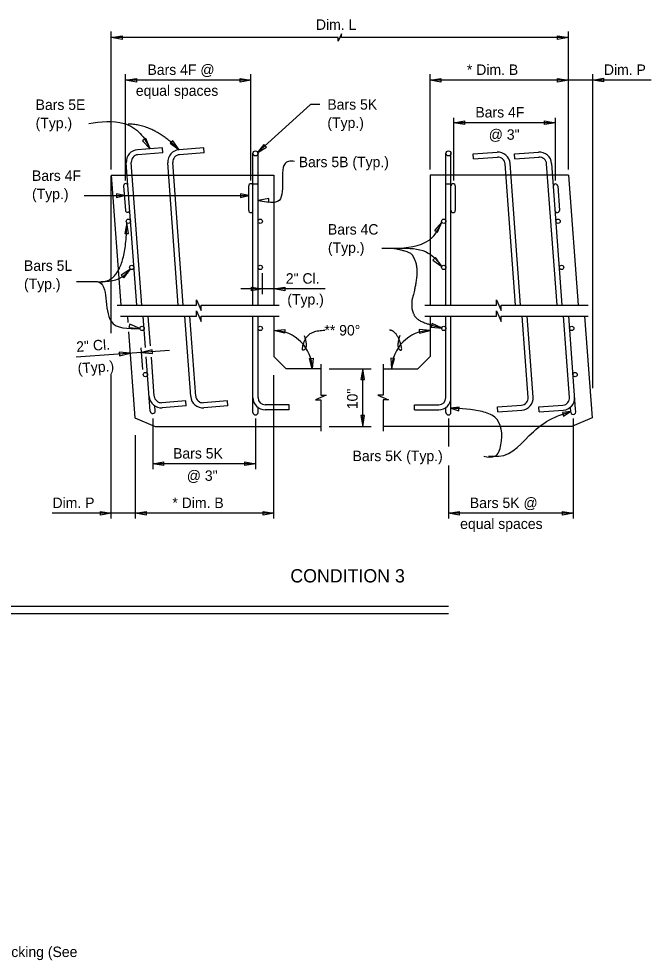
# Model space of a CAD drawing. Extents: x 0.5 to 29.5, y 0.9 to 17.7.
# Drawn here: x 20.37 to 29.51, y 4.1 to 17.7 of the extents above; entities that cross this region are included whole.
import ezdxf

# ---------------------------------------------------------------- set-up
doc = ezdxf.new("R2010")
doc.units = 0
for name, color, linetype in [('BeamConc', 7, 'Continuous'), ('Dimension', 7, 'Continuous'), ('Rebar', 7, 'Continuous'), ('TextStructures', 7, 'Continuous')]:
    doc.layers.add(name, color=color, linetype=linetype)

# ---------------------------------------------------------------- blocks, each defined once
blk = doc.blocks.new('Terminator-Arrow')
at = {"layer": 'Dimension'}
blk.add_lwpolyline([(0, 0), (-0.00041, 0.000069), (-0.00041, -0.000069)], close=True, dxfattribs=at)

msp = doc.modelspace()

# ---------------------------------------------------------------- linework, layer by layer
at = {"layer": 'BeamConc'}
for p, q in [((21.701, 15.447), (24.052, 15.447)), ((21.701, 15.447), (21.84, 13.569)), ((24.052, 15.447), (24.052, 13.569)), ((28.309, 15.447), (26.309, 15.447)), ((26.309, 15.447), (26.309, 13.569)), ((28.309, 15.447), (28.448, 13.569)), ((21.935, 13.407), (21.941, 13.316)), ((24.052, 13.407), (24.052, 12.825)), ((26.309, 13.407), (26.309, 12.825)), ((28.542, 13.407), (28.651, 11.94)), ((21.951, 13.183), (22.043, 11.94)), ((24.229, 12.648), (24.052, 12.825)), ((26.132, 12.648), (26.309, 12.825)), ((24.729, 12.648), (24.229, 12.648)), ((25.632, 12.648), (26.132, 12.648)), ((22.043, 11.94), (22.335, 11.815)), ((28.651, 11.94), (28.359, 11.815)), ((22.335, 11.815), (24.729, 11.815)), ((28.359, 11.815), (25.632, 11.815))]:
    msp.add_line(p, q, dxfattribs=at)
at = {"layer": 'Dimension'}
for p, q in [((21.701, 15.529), (21.701, 17.519)), ((21.701, 15.529), (21.701, 17.519)), ((28.309, 15.529), (28.309, 17.519)), ((28.309, 15.529), (28.309, 17.519)), ((21.909, 15.368), (21.909, 16.903)), ((21.909, 15.368), (21.909, 16.903)), ((23.719, 15.368), (23.719, 16.903)), ((23.719, 15.368), (23.719, 16.903)), ((26.309, 15.529), (26.309, 16.903)), ((26.309, 15.529), (26.309, 16.903)), ((28.66, 12.37), (28.66, 16.903)), ((28.66, 12.37), (28.66, 16.903)), ((23.719, 16.819), (21.909, 16.819)), ((23.719, 16.819), (21.909, 16.819)), ((29.505, 16.819), (26.309, 16.819)), ((29.505, 16.819), (26.309, 16.819)), ((26.651, 15.368), (26.651, 16.274)), ((26.651, 15.368), (26.651, 16.274)), ((28.12, 16.204), (26.651, 16.204)), ((28.12, 16.204), (26.651, 16.204)), ((28.12, 15.368), (28.12, 16.274)), ((28.12, 15.368), (28.12, 16.274)), ((21.701, 13.161), (21.701, 15.433)), ((21.701, 13.161), (21.701, 15.433)), ((21.308, 15.151), (23.687, 15.151)), ((21.308, 15.151), (23.687, 15.151)), ((23.885, 13.728), (23.885, 14.029)), ((23.885, 13.728), (23.885, 14.029)), ((24.794, 13.803), (23.575, 13.803)), ((24.794, 13.803), (23.575, 13.803)), ((22.158, 12.639), (22.136, 12.949)), ((22.158, 12.639), (22.136, 12.949)), ((22.541, 12.914), (21.193, 12.814)), ((22.541, 12.914), (21.193, 12.814)), ((21.701, 10.485), (21.701, 12.564)), ((21.701, 10.485), (21.701, 12.564)), ((24.052, 10.485), (24.052, 12.556)), ((24.052, 10.485), (24.052, 12.556)), ((24.851, 12.648), (25.459, 12.648)), ((24.851, 12.648), (25.459, 12.648)), ((25.338, 11.815), (25.338, 12.648)), ((25.338, 11.815), (25.338, 12.648)), ((22.302, 11.932), (22.302, 11.2)), ((22.302, 11.932), (22.302, 11.2)), ((23.786, 11.932), (23.786, 11.2)), ((23.786, 11.932), (23.786, 11.2)), ((26.575, 11.932), (26.575, 11.526)), ((26.575, 11.932), (26.575, 11.526)), ((28.378, 11.932), (28.378, 10.485)), ((28.378, 11.932), (28.378, 10.485)), ((24.851, 11.815), (25.459, 11.815)), ((24.851, 11.815), (25.459, 11.815)), ((22.052, 10.485), (22.052, 11.687)), ((22.052, 10.485), (22.052, 11.687)), ((23.786, 11.276), (22.302, 11.276)), ((23.786, 11.276), (22.302, 11.276)), ((26.575, 11.253), (26.575, 10.485)), ((26.575, 11.253), (26.575, 10.485)), ((24.052, 10.561), (20.846, 10.561)), ((24.052, 10.561), (20.846, 10.561)), ((28.378, 10.561), (26.575, 10.561)), ((28.378, 10.561), (26.575, 10.561)), ((26.575, 9.216), (18.476, 9.216)), ((26.575, 9.216), (18.476, 9.216)), ((26.575, 9.108), (18.476, 9.108)), ((26.575, 9.108), (18.476, 9.108))]:
    msp.add_line(p, q, dxfattribs=at)
for points in [[(28.309, 17.434), (25.028, 17.434), (25.028, 17.486), (25.005, 17.434), (24.983, 17.382), (24.983, 17.434), (21.701, 17.434)], [(28.309, 17.434), (25.028, 17.434), (25.028, 17.486), (25.005, 17.434), (24.983, 17.382), (24.983, 17.434), (21.701, 17.434)], [(24.716, 16.469), (24.583, 16.469), (23.812, 15.766)], [(24.716, 16.469), (24.583, 16.469), (23.812, 15.766)], [(21.787, 13.569), (22.934, 13.569), (22.934, 13.646), (22.968, 13.569), (23.002, 13.491), (23.002, 13.569), (24.128, 13.569)], [(21.787, 13.569), (22.934, 13.569), (22.934, 13.646), (22.968, 13.569), (23.002, 13.491), (23.002, 13.569), (24.128, 13.569)], [(26.234, 13.569), (27.269, 13.569), (27.269, 13.646), (27.303, 13.569), (27.336, 13.491), (27.336, 13.569), (28.594, 13.569)], [(26.234, 13.569), (27.269, 13.569), (27.269, 13.646), (27.303, 13.569), (27.336, 13.491), (27.336, 13.569), (28.594, 13.569)], [(21.835, 13.407), (22.934, 13.407), (22.934, 13.484), (22.968, 13.407), (23.002, 13.329), (23.002, 13.407), (24.128, 13.407)], [(21.835, 13.407), (22.934, 13.407), (22.934, 13.484), (22.968, 13.407), (23.002, 13.329), (23.002, 13.407), (24.128, 13.407)], [(26.234, 13.407), (27.269, 13.407), (27.269, 13.484), (27.303, 13.407), (27.336, 13.329), (27.336, 13.407), (28.594, 13.407)], [(26.234, 13.407), (27.269, 13.407), (27.269, 13.484), (27.303, 13.407), (27.336, 13.329), (27.336, 13.407), (28.594, 13.407)], [(24.729, 12.715), (24.729, 12.265), (24.807, 12.265), (24.652, 12.198), (24.729, 12.198), (24.729, 11.748)], [(24.729, 12.715), (24.729, 12.265), (24.807, 12.265), (24.652, 12.198), (24.729, 12.198), (24.729, 11.748)], [(25.632, 12.715), (25.632, 12.265), (25.554, 12.265), (25.709, 12.198), (25.632, 12.198), (25.632, 11.748)], [(25.632, 12.715), (25.632, 12.265), (25.554, 12.265), (25.709, 12.198), (25.632, 12.198), (25.632, 11.748)]]:
    msp.add_lwpolyline(points, dxfattribs=at)
for points in [[(22.262, 15.827), (22.2, 15.973), (22.155, 15.944)], [(22.262, 15.827), (22.2, 15.973), (22.155, 15.944)], [(22.682, 15.814), (22.591, 15.943), (22.553, 15.906)], [(22.682, 15.814), (22.591, 15.943), (22.553, 15.906)], [(23.812, 15.766), (23.945, 15.852), (23.909, 15.891)], [(23.812, 15.766), (23.945, 15.852), (23.909, 15.891)], [(21.893, 15.151), (21.776, 15.177), (21.776, 15.124)], [(21.893, 15.151), (21.776, 15.177), (21.776, 15.124)], [(23.688, 15.151), (23.57, 15.177), (23.57, 15.124)], [(23.688, 15.151), (23.57, 15.177), (23.57, 15.124)], [(23.823, 15.082), (23.979, 15.056), (23.979, 15.109)], [(23.823, 15.082), (23.979, 15.056), (23.979, 15.109)], [(21.927, 14.758), (21.899, 14.602), (21.952, 14.602)], [(21.927, 14.758), (21.899, 14.602), (21.952, 14.602)], [(26.479, 14.766), (26.374, 14.648), (26.418, 14.62)], [(26.479, 14.766), (26.374, 14.648), (26.418, 14.62)], [(26.479, 14.127), (26.387, 14.256), (26.349, 14.218)], [(26.479, 14.127), (26.387, 14.256), (26.349, 14.218)], [(21.979, 14.089), (21.847, 14.002), (21.883, 13.963)], [(21.979, 14.089), (21.847, 14.002), (21.883, 13.963)], [(22.115, 13.231), (21.969, 13.294), (21.957, 13.243)], [(22.115, 13.231), (21.969, 13.294), (21.957, 13.243)], [(24.052, 13.201), (24.21, 13.215), (24.205, 13.162)], [(24.052, 13.201), (24.21, 13.215), (24.205, 13.162)], [(26.309, 13.201), (26.151, 13.215), (26.156, 13.162)], [(26.309, 13.201), (26.151, 13.215), (26.156, 13.162)], [(26.484, 13.237), (26.339, 13.302), (26.326, 13.251)], [(26.484, 13.237), (26.339, 13.302), (26.326, 13.251)], [(22.14, 12.884), (22.298, 12.869), (22.294, 12.922)], [(22.14, 12.884), (22.298, 12.869), (22.294, 12.922)], [(21.974, 12.872), (21.816, 12.887), (21.82, 12.834)], [(21.974, 12.872), (21.816, 12.887), (21.82, 12.834)], [(24.607, 12.646), (24.566, 12.799), (24.618, 12.804)], [(24.607, 12.646), (24.566, 12.799), (24.618, 12.804)], [(25.754, 12.646), (25.796, 12.799), (25.743, 12.804)], [(25.754, 12.646), (25.796, 12.799), (25.743, 12.804)], [(25.338, 12.648), (25.311, 12.492), (25.364, 12.492)], [(25.338, 12.648), (25.311, 12.492), (25.364, 12.492)], [(25.338, 11.815), (25.364, 11.971), (25.311, 11.971)], [(25.338, 11.815), (25.364, 11.971), (25.311, 11.971)], [(26.611, 12.079), (26.725, 12.04), (26.731, 12.092)], [(26.611, 12.079), (26.725, 12.04), (26.731, 12.092)], [(28.341, 12.03), (28.222, 12.015), (28.24, 11.966)], [(28.341, 12.03), (28.222, 12.015), (28.24, 11.966)]]:
    msp.add_lwpolyline(points, close=True, dxfattribs=at)
for centre, start, end in [((24.048, 12.642), 0.3991, 89.55), ((24.048, 12.642), 0.3991, 89.55), ((26.314, 12.642), 90.45, 179.6009), ((26.314, 12.642), 90.45, 179.6009)]:
    msp.add_arc(centre, 0.559, start, end, dxfattribs=at)
for points in [[(21.375, 16.192), (21.889, 16.192), (22.119, 16.049), (22.262, 15.827)], [(21.375, 16.192), (21.889, 16.192), (22.119, 16.049), (22.262, 15.827)], [(24.351, 15.644), (24.261, 15.644), (24.129, 15.082), (23.823, 15.082)], [(24.351, 15.644), (24.261, 15.644), (24.129, 15.082), (23.823, 15.082)], [(25.614, 14.391), (25.866, 14.391), (26.341, 14.547), (26.479, 14.766)], [(25.614, 14.391), (25.866, 14.391), (26.341, 14.547), (26.479, 14.766)], [(25.737, 14.391), (25.928, 14.392), (26.284, 14.321), (26.479, 14.127)], [(25.737, 14.391), (25.928, 14.392), (26.284, 14.321), (26.479, 14.127)], [(21.198, 13.907), (21.447, 13.907), (21.86, 13.978), (21.979, 14.089)], [(21.198, 13.907), (21.447, 13.907), (21.86, 13.978), (21.979, 14.089)], [(21.405, 13.907), (21.499, 13.908), (21.698, 13.334), (22.115, 13.231)], [(21.405, 13.907), (21.499, 13.908), (21.698, 13.334), (22.115, 13.231)], [(27.085, 11.385), (27.246, 11.385), (27.334, 11.55), (27.243, 11.95), (27.063, 12.029), (26.611, 12.079)], [(27.085, 11.385), (27.246, 11.385), (27.334, 11.55), (27.243, 11.95), (27.063, 12.029), (26.611, 12.079)], [(27.153, 11.385), (27.26, 11.385), (27.301, 11.385), (27.802, 11.739), (28.117, 11.95), (28.341, 12.03)], [(27.153, 11.385), (27.26, 11.385), (27.301, 11.385), (27.802, 11.739), (28.117, 11.95), (28.341, 12.03)]]:
    msp.add_spline(points, degree=3, dxfattribs=at)
for points in [[(22.682, 15.814), (22.313, 16.184), (21.945, 16.184)], [(22.682, 15.814), (22.313, 16.184), (21.945, 16.184)], [(21.551, 13.905), (21.918, 13.905), (21.927, 14.758)], [(21.551, 13.905), (21.918, 13.905), (21.927, 14.758)], [(25.776, 14.391), (25.996, 14.346), (26.07, 14.28), (26.133, 14.084), (26.083, 13.76), (26.045, 13.645), (26.045, 13.561), (26.045, 13.508), (26.098, 13.374), (26.266, 13.293), (26.484, 13.237)], [(25.776, 14.391), (25.996, 14.346), (26.07, 14.28), (26.133, 14.084), (26.083, 13.76), (26.045, 13.645), (26.045, 13.561), (26.045, 13.508), (26.098, 13.374), (26.266, 13.293), (26.484, 13.237)], [(24.49, 13.129), (24.547, 12.957), (24.436, 12.888), (24.549, 13.205), (24.789, 13.205)], [(24.49, 13.129), (24.547, 12.957), (24.436, 12.888), (24.549, 13.205), (24.789, 13.205)], [(25.873, 13.129), (25.816, 12.957), (25.927, 12.888), (25.814, 13.205), (25.723, 13.205)], [(25.873, 13.129), (25.816, 12.957), (25.927, 12.888), (25.814, 13.205), (25.723, 13.205)]]:
    msp.add_open_spline(points, degree=2, dxfattribs=at)
at = {"layer": 'Rebar'}
for p, q in [((22.44, 15.84), (22.082, 15.814)), ((22.445, 15.767), (22.44, 15.84)), ((23.04, 15.84), (22.682, 15.814)), ((23.045, 15.767), (23.04, 15.84)), ((26.93, 15.753), (27.277, 15.778)), ((27.53, 15.753), (27.877, 15.778)), ((22.445, 15.767), (22.087, 15.741)), ((23.045, 15.767), (22.687, 15.741)), ((23.75, 13.569), (23.75, 15.76)), ((23.823, 13.569), (23.823, 15.76)), ((26.538, 13.569), (26.538, 15.76)), ((26.611, 13.569), (26.611, 15.76)), ((26.936, 15.68), (26.93, 15.753)), ((26.936, 15.68), (27.283, 15.706)), ((27.536, 15.68), (27.53, 15.753)), ((27.536, 15.68), (27.883, 15.706)), ((22.07, 13.569), (21.918, 15.624)), ((22.143, 13.569), (21.991, 15.629)), ((22.67, 13.569), (22.518, 15.624)), ((22.743, 13.569), (22.591, 15.629)), ((27.545, 13.569), (27.394, 15.609)), ((27.618, 13.569), (27.467, 15.615)), ((28.145, 13.569), (27.994, 15.609)), ((28.218, 13.569), (28.067, 15.615)), ((21.88, 15.29), (21.906, 14.937)), ((23.687, 15.29), (23.687, 14.936)), ((23.75, 15.322), (23.823, 15.322)), ((26.538, 15.322), (26.611, 15.322)), ((26.674, 15.29), (26.674, 14.936)), ((28.154, 15.29), (28.18, 14.937)), ((22.198, 12.955), (22.164, 13.407)), ((22.269, 12.979), (22.237, 13.407)), ((22.85, 12.249), (22.764, 13.407)), ((22.922, 12.254), (22.837, 13.407)), ((23.75, 12.018), (23.75, 13.407)), ((23.823, 12.231), (23.823, 13.407)), ((26.538, 12.231), (26.538, 13.407)), ((26.611, 12.054), (26.611, 13.407)), ((27.726, 12.235), (27.639, 13.407)), ((27.799, 12.24), (27.713, 13.407)), ((28.326, 12.235), (28.239, 13.407)), ((28.412, 12.063), (28.313, 13.407)), ((22.265, 12.036), (22.207, 12.822)), ((22.322, 12.254), (22.281, 12.816)), ((22.338, 12.042), (22.333, 12.112)), ((22.781, 12.184), (22.434, 12.158)), ((22.786, 12.111), (22.439, 12.086)), ((22.786, 12.111), (22.781, 12.184)), ((23.381, 12.184), (23.034, 12.158)), ((23.386, 12.111), (23.039, 12.086)), ((23.386, 12.111), (23.381, 12.184)), ((24.275, 12.127), (23.927, 12.127)), ((24.275, 12.054), (24.275, 12.127)), ((26.086, 12.127), (26.434, 12.127)), ((26.086, 12.054), (26.086, 12.127)), ((27.283, 12.097), (27.63, 12.123)), ((27.883, 12.097), (28.23, 12.123)), ((23.823, 12.018), (23.823, 12.088)), ((24.275, 12.054), (23.927, 12.054)), ((26.086, 12.054), (26.434, 12.054)), ((26.538, 12.018), (26.538, 12.088)), ((26.611, 12.018), (26.611, 12.054)), ((27.288, 12.025), (27.283, 12.097)), ((27.288, 12.025), (27.635, 12.05)), ((27.888, 12.025), (27.883, 12.097)), ((27.888, 12.025), (28.235, 12.05)), ((28.342, 12.022), (28.337, 12.092)), ((28.415, 12.027), (28.412, 12.063))]:
    msp.add_line(p, q, dxfattribs=at)
for centre, radius in [((23.786, 15.761), 0.0365), ((26.575, 15.761), 0.0365), ((21.949, 14.78), 0.0312), ((23.854, 14.78), 0.0312), ((26.507, 14.78), 0.0312), ((28.16, 14.78), 0.0312), ((21.998, 14.113), 0.0312), ((23.854, 14.113), 0.0312), ((26.507, 14.113), 0.0312), ((28.209, 14.113), 0.0312), ((22.146, 13.231), 0.0312), ((23.854, 13.231), 0.0312), ((26.507, 13.231), 0.0312), ((28.357, 13.231), 0.0312), ((22.195, 12.565), 0.0312), ((28.406, 12.565), 0.0312)]:
    msp.add_circle(centre, radius, dxfattribs=at)
for centre, radius, start, end in [((22.095, 15.637), 0.177, 94.2234, 184.2234), ((22.695, 15.637), 0.177, 94.2234, 184.2234), ((27.29, 15.602), 0.177, 4.2232, 94.2232), ((27.89, 15.602), 0.177, 4.2232, 94.2232), ((22.095, 15.637), 0.104, 94.2234, 184.2234), ((22.695, 15.637), 0.104, 94.2234, 184.2234), ((27.29, 15.602), 0.104, 4.2232, 94.2232), ((27.89, 15.602), 0.104, 4.2232, 94.2232), ((21.911, 15.293), 0.0312, 4.2234, 184.2234), ((23.719, 15.29), 0.0312, 0, 180), ((26.643, 15.29), 0.0312, 0, 180), ((28.122, 15.288), 0.0312, 4.2232, 184.2232), ((21.937, 14.94), 0.0312, 184.2234, 4.2234), ((23.719, 14.936), 0.0312, 180, 0), ((26.643, 14.936), 0.0312, 180, 0), ((28.149, 14.935), 0.0312, 184.2232, 4.2232), ((22.426, 12.262), 0.177, 184.2234, 274.2234), ((22.426, 12.262), 0.104, 184.2234, 274.2234), ((23.026, 12.262), 0.177, 184.2234, 274.2234), ((23.026, 12.262), 0.104, 184.2234, 274.2234), ((23.927, 12.231), 0.177, 180, 270), ((23.927, 12.231), 0.104, 180, 270), ((26.434, 12.231), 0.104, 270, 0), ((26.434, 12.231), 0.177, 270, 0), ((27.622, 12.227), 0.104, 274.2232, 4.2232), ((27.622, 12.227), 0.177, 274.2232, 4.2232), ((28.222, 12.227), 0.104, 274.2232, 4.2232), ((28.222, 12.227), 0.177, 274.2232, 4.2232), ((22.302, 12.039), 0.0365, 184.2234, 4.2234), ((23.786, 12.018), 0.0365, 180, 0), ((26.575, 12.018), 0.0365, 180, 0), ((28.378, 12.024), 0.0365, 184.2232, 4.2232)]:
    msp.add_arc(centre, radius, start, end, dxfattribs=at)

# ---------------------------------------------------------------- block references
at = {"layer": 'Dimension', "xscale": 381, "yscale": -384.0238095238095, "rotation": 180}
for p in [(21.701, 17.434), (21.701, 17.434), (21.909, 16.818), (21.909, 16.818), (26.309, 16.818), (26.309, 16.818), (28.66, 16.819), (28.66, 16.819), (26.651, 16.203), (26.651, 16.203), (24.052, 13.803), (24.052, 13.803), (22.302, 11.275), (22.302, 11.275), (22.052, 10.56), (22.052, 10.56), (26.575, 10.56), (26.575, 10.56)]:
    msp.add_blockref('Terminator-Arrow', p, dxfattribs=at)
at = {"layer": 'Dimension', "xscale": 381, "yscale": -384.0238095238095}
for p in [(28.309, 17.433), (28.309, 17.433), (23.719, 16.818), (23.719, 16.818), (28.309, 16.818), (28.309, 16.818), (28.12, 16.203), (28.12, 16.203), (23.886, 13.803), (23.886, 13.803), (23.786, 11.275), (23.786, 11.275), (21.701, 10.56), (21.701, 10.56), (24.052, 10.56), (24.052, 10.56), (28.378, 10.56), (28.378, 10.56)]:
    msp.add_blockref('Terminator-Arrow', p, dxfattribs=at)

# ---------------------------------------------------------------- texts
at = {"layer": 'Dimension'}
for s, p in [('Bars 5E', (20.608, 16.388)), ('Bars 5K', (24.825, 16.392)), ('(Typ.)', (20.608, 16.124)), ('(Typ.)', (24.825, 16.128)), ('Bars 4F', (20.556, 15.363)), ('(Typ.)', (20.556, 15.099)), ('Bars 4C', (24.833, 14.587)), ('(Typ.)', (24.833, 14.323)), ('Bars 5L', (20.44, 14.063)), ('(Typ.)', (20.44, 13.799)), ('Temporary Blocking (See ', (18.931, 4.149))]:
    msp.add_text(s, height=0.1512, dxfattribs=at).set_placement(p)
at = {"layer": 'TextStructures'}
for s, height, p in [('Dim. L', 0.1512, (24.66, 17.545)), ('Bars 4F @', 0.1512, (22.225, 16.894)), ('* Dim. B', 0.1512, (26.842, 16.894)), ('Dim. P', 0.1512, (28.822, 16.894)), ('equal spaces', 0.1512, (22.057, 16.592)), ('Bars 4F', 0.1512, (26.964, 16.279)), ('@ 3"', 0.1512, (27.157, 15.957)), ('Bars 5B (Typ.)', 0.1512, (24.411, 15.561)), ('2" Cl.', 0.1512, (24.224, 13.878)), ('(Typ.)', 0.1512, (24.246, 13.576)), ('** 90°', 0.1512, (24.782, 13.129)), ('Bars 5K', 0.1512, (22.595, 11.351)), ('Bars 5K (Typ.)', 0.1512, (25.189, 11.314)), ('@ 3"', 0.1512, (22.793, 11.029)), ('Dim. P', 0.1512, (20.852, 10.636)), ('* Dim. B', 0.1512, (22.585, 10.636)), ('Bars 5K @', 0.1512, (26.884, 10.636)), ('equal spaces', 0.1512, (26.744, 10.334)), ('CONDITION 3', 0.192, (24.29, 9.561))]:
    msp.add_text(s, height=height, dxfattribs=at).set_placement(p)
for s, rotation, p in [('2" Cl.', 4.2234, (21.202, 12.891)), ('(Typ.)', 4.2234, (21.221, 12.577)), ('10"', 90, (25.262, 12.064))]:
    msp.add_text(s, height=0.1512, rotation=rotation, dxfattribs=at).set_placement(p)

doc.saveas('drawing.dxf')
